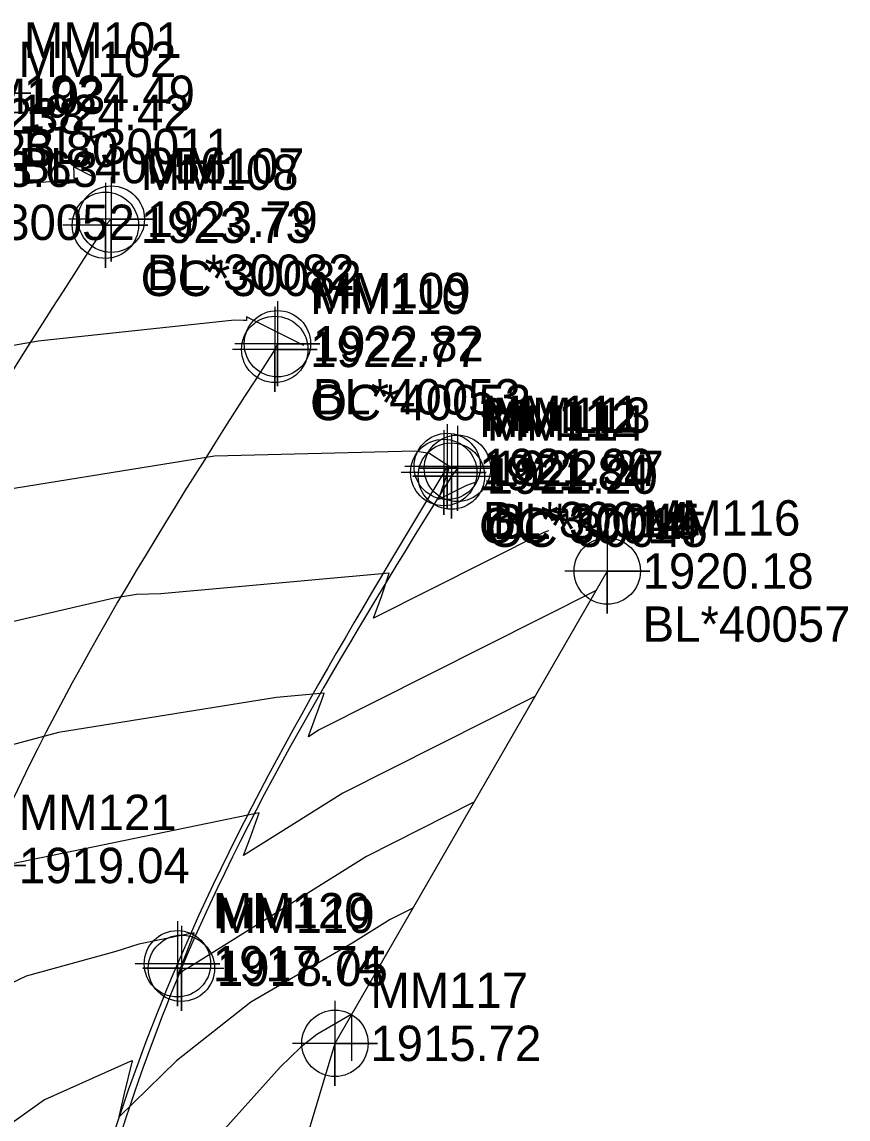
# Model space of a CAD drawing. Extents: x 1004378 to 1005103, y 553854 to 554288.
# Drawn here: x 1005044.7 to 1005103.1, y 554194.9 to 554272.4 of the extents above; entities that cross this region are included whole.
import ezdxf

# ---------------------------------------------------------------- set-up
doc = ezdxf.new("R2010")
doc.units = 0
for name, color, linetype in [('DTM Contours Major', 7, 'Continuous'), ('DTM Contours Minor', 7, 'Continuous'), ('Exist DTM Breakline', 7, 'Continuous'), ('Exist DTM Breakline Cogo Comment', 7, 'Continuous'), ('Exist DTM Breakline Cogo Elevation', 7, 'Continuous'), ('Exist DTM Breakline Cogo Number', 7, 'Continuous'), ('Exist DTM Breakline Cogo Point CELL', 7, 'Continuous'), ('Exist DTM Crownline', 7, 'Continuous'), ('Exist DTM Crownline Cogo Comment', 7, 'Continuous'), ('Exist DTM Crownline Cogo Elevation', 7, 'Continuous'), ('Exist DTM Crownline Cogo Number', 7, 'Continuous'), ('Exist DTM Crownline Cogo Point CELL', 7, 'Continuous'), ('Exist Roads Curbs', 7, 'Continuous'), ('Exist Roads Curbs Cogo Comment', 7, 'Continuous'), ('Exist Roads Curbs Cogo Elevation', 7, 'Continuous'), ('Exist Roads Curbs Cogo Number', 7, 'Continuous'), ('Exist Roads Curbs Cogo Point CELL', 7, 'Continuous'), ('Exist Roads EOP', 7, 'Continuous'), ('Exist Roads EOP Cogo Comment', 7, 'Continuous'), ('Exist Roads EOP Cogo Elevation', 7, 'Continuous'), ('Exist Roads EOP Cogo Number', 7, 'Continuous'), ('Exist Roads EOP Cogo Point CELL', 7, 'Continuous'), ('Exist Roads Soil Cogo Comment', 7, 'Continuous'), ('Exist Roads Soil Cogo Elevation', 7, 'Continuous'), ('Exist Roads Soil Cogo Number', 7, 'Continuous')]:
    doc.layers.add(name, color=color, linetype=linetype)

msp = doc.modelspace()

# ---------------------------------------------------------------- linework, layer by layer
at = {"layer": 'DTM Contours Major'}
msp.add_lwpolyline([(1005085.253, 554232.251), (1005065.7, 554222.397), (1005064.933, 554221.918), (1005064.991, 554222.066), (1005065.344, 554223.049), (1005065.952, 554224.718), (1005066.048, 554225.004), (1005062.678, 554224.698), (1005047.268, 554222.206), (1005031.925, 554218.126), (1005030.77, 554217.777), (1005026.361, 554215.994), (1005026.142, 554215.905), (1005025.965, 554215.797), (1005018.761, 554211.473), (1005015.099, 554208.571), (1005013.055, 554206.965), (1005008.097, 554202.389), (1005006.285, 554199.827), (1005002.41, 554197.77), (1005001.113, 554195.406)], dxfattribs=at)
at = {"layer": 'DTM Contours Minor'}
for points in [[(1005049.674, 554261.493), (1005048.336, 554262.162), (1005048.391, 554261.154), (1005047.971, 554261.002), (1005047.219, 554261.151), (1005038.078, 554260.42), (1005037.81, 554261.029), (1005038.533, 554264.244), (1005038.474, 554264.547), (1005022.134, 554266.393), (1005018.739, 554266.663), (1005008.512, 554259.857), (1005006.97, 554257.736), (1005007.666, 554257.334), (1005003.478, 554254.686), (1004999.082, 554247.727), (1005001.345, 554242.184), (1004999.666, 554238.402), (1004998.854, 554234.12), (1004998.544, 554224.321), (1004997.101, 554219.058), (1004994.148, 554215.354), (1004993.153, 554201.493), (1004985.717, 554187.945)], [(1005064.608, 554249.551), (1005060.552, 554251.578), (1005060.567, 554251.311), (1005060.348, 554251.327), (1005059.72, 554251.352), (1005045.835, 554249.855), (1005031.335, 554247.323)], [(1005076.842, 554239.926), (1005076.104, 554239.672), (1005074.128, 554238.68), (1005074.219, 554238.931), (1005074.736, 554240.465), (1005074.839, 554240.777), (1005074.933, 554240.972), (1005073.435, 554241.951), (1005073.343, 554241.956), (1005072.44, 554242.077), (1005058.295, 554241.729), (1005039.877, 554238.78)], [(1005081.907, 554236.456), (1005081.575, 554236.342), (1005069.531, 554230.299), (1005070.085, 554231.824), (1005070.64, 554233.472), (1005054.504, 554232.01), (1005052.782, 554231.968), (1005051.198, 554231.714), (1005032.836, 554227.453), (1005025.92, 554225.538), (1005021.623, 554223.448), (1005019.859, 554222.732), (1005013.96, 554219.101), (1005012.402, 554218.937), (1005011.71, 554216.413), (1005004.54, 554207.42), (1005004.489, 554206.704), (1004992.311, 554184.516)], [(1005080.939, 554224.769), (1005067.37, 554217.93), (1005060.336, 554213.536), (1005060.866, 554214.898), (1005061.455, 554216.534), (1005042.381, 554212.616), (1005041.766, 554212.425), (1005037.72, 554211.199), (1005036.548, 554210.725), (1005032.718, 554208.659), (1005027.609, 554206.201), (1005022.187, 554202.253), (1005021.549, 554201.814), (1005020.689, 554201.039), (1005013.957, 554194.829)], [(1005076.625, 554217.286), (1005069.041, 554213.464), (1005056.52, 554205.643), (1005056.186, 554205.45), (1005055.751, 554205.106), (1005055.8, 554205.258), (1005055.916, 554205.611), (1005056.742, 554207.729), (1005056.863, 554208.065), (1005052.951, 554207.261), (1005051.317, 554206.753), (1005044.981, 554205.003), (1005038.321, 554201.832), (1005037.92, 554201.653), (1005037.066, 554201.044), (1005029.069, 554195.542), (1005025.438, 554192.269)], [(1005072.311, 554209.804), (1005070.712, 554208.998), (1005068.073, 554207.35), (1005060.854, 554203.169), (1005055.614, 554199.027), (1005051.563, 554195.07), (1005051.936, 554196.712), (1005052.473, 554198.935), (1005052.494, 554198.998), (1005052.502, 554199.025), (1005052.396, 554198.996), (1005052.336, 554198.967), (1005046.282, 554196.261), (1005040.238, 554191.952)], [(1005068.005, 554199.026), (1005067.997, 554202.322), (1005065.521, 554200.888), (1005064.389, 554199.993), (1005062.927, 554198.566), (1005053.023, 554187.546)]]:
    msp.add_lwpolyline(points, dxfattribs=at)
at = {"layer": 'Exist DTM Breakline'}
msp.add_line((1005062.742, 554249.68), (1005062.556, 554249.275), dxfattribs=at)
msp.add_lwpolyline([(1005086.044, 554233.622), (1005066.807, 554200.26), (1005058.407, 554172.308), (1005052.455, 554140.645), (1005052.437, 554096.336), (1005050.24, 554053.656), (1005047.48, 554010.1), (1005047.57, 553964.54), (1005045.226, 553915.523), (1005033.752, 553871.735)], dxfattribs=at)
msp.add_spline([(1005062.556, 554249.275), (1005041.97, 554212.824), (1005032.11, 554179.915), (1005026.833, 554146.301), (1005025.779, 554104.318), (1005027.497, 554055.674)], degree=3, dxfattribs=at)
at = {"layer": 'Exist DTM Breakline Cogo Point CELL'}
for points in [[(1005041.953, 554269.011), (1005041.953, 554263.011), (1005041.953, 554266.011), (1005044.953, 554266.011), (1005038.953, 554266.011)], [(1005062.556, 554252.275), (1005062.556, 554246.275), (1005062.556, 554249.275), (1005065.556, 554249.275), (1005059.556, 554249.275)], [(1005062.742, 554252.68), (1005062.742, 554246.68), (1005062.742, 554249.68), (1005065.742, 554249.68), (1005059.742, 554249.68)], [(1005086.044, 554236.622), (1005086.044, 554230.622), (1005086.044, 554233.622), (1005089.044, 554233.622), (1005083.044, 554233.622)], [(1005041.97, 554215.824), (1005041.97, 554209.824), (1005041.97, 554212.824), (1005044.97, 554212.824), (1005038.97, 554212.824)], [(1005066.807, 554203.26), (1005066.807, 554197.26), (1005066.807, 554200.26), (1005069.807, 554200.26), (1005063.807, 554200.26)]]:
    msp.add_lwpolyline(points, dxfattribs=at)
for centre in [(1005062.742, 554249.68), (1005062.556, 554249.275), (1005086.044, 554233.622), (1005066.807, 554200.26)]:
    msp.add_circle(centre, 2.344, dxfattribs=at)
at = {"layer": 'Exist DTM Crownline'}
msp.add_line((1005051.005, 554258.476), (1005050.587, 554258.044), dxfattribs=at)
msp.add_spline([(1005050.587, 554258.044), (1005028.479, 554219.945), (1005017.046, 554183.931), (1005013.967, 554147.492), (1005013.771, 554103.753), (1005015.769, 554055.214)], degree=3, dxfattribs=at)
at = {"layer": 'Exist DTM Crownline Cogo Point CELL'}
for points in [[(1005051.005, 554261.476), (1005051.005, 554255.476), (1005051.005, 554258.476), (1005054.005, 554258.476), (1005048.005, 554258.476)], [(1005050.587, 554261.044), (1005050.587, 554255.044), (1005050.587, 554258.044), (1005053.587, 554258.044), (1005047.587, 554258.044)]]:
    msp.add_lwpolyline(points, dxfattribs=at)
for centre in [(1005051.005, 554258.476), (1005050.587, 554258.044)]:
    msp.add_circle(centre, 2.344, dxfattribs=at)
at = {"layer": 'Exist Roads Curbs'}
msp.add_line((1005075.456, 554240.876), (1005075.03, 554240.325), dxfattribs=at)
msp.add_spline([(1005075.03, 554240.325), (1005055.961, 554205.561), (1005046.997, 554176.639), (1005041.862, 554143.203), (1005041.439, 554133.575)], degree=3, dxfattribs=at)
at = {"layer": 'Exist Roads Curbs Cogo Point CELL'}
for points in [[(1005075.456, 554243.876), (1005075.456, 554237.876), (1005075.456, 554240.876), (1005072.726, 554240.876), (1005078.456, 554240.876)], [(1005075.03, 554243.325), (1005075.03, 554237.325), (1005075.03, 554240.325), (1005072.3, 554240.325), (1005078.03, 554240.325)], [(1005055.961, 554208.561), (1005055.961, 554202.561), (1005055.961, 554205.561), (1005053.23, 554205.561), (1005058.961, 554205.561)]]:
    msp.add_lwpolyline(points, dxfattribs=at)
for centre in [(1005075.03, 554240.325), (1005075.456, 554240.876), (1005055.961, 554205.561)]:
    msp.add_circle(centre, 2.344, dxfattribs=at)
at = {"layer": 'Exist Roads EOP'}
msp.add_line((1005074.741, 554241.007), (1005074.494, 554240.581), dxfattribs=at)
msp.add_spline([(1005074.494, 554240.581), (1005055.678, 554205.88), (1005046.35, 554176.623), (1005041.386, 554143.248), (1005040.93, 554132.857)], degree=3, dxfattribs=at)
at = {"layer": 'Exist Roads EOP Cogo Point CELL'}
for points in [[(1005042.326, 554270.369), (1005042.326, 554264.369), (1005042.326, 554267.369), (1005045.326, 554267.369), (1005039.326, 554267.369)], [(1005074.494, 554243.581), (1005074.494, 554237.581), (1005074.494, 554240.581), (1005077.494, 554240.581), (1005071.494, 554240.581)], [(1005074.741, 554244.007), (1005074.741, 554238.007), (1005074.741, 554241.007), (1005077.741, 554241.007), (1005071.741, 554241.007)], [(1005055.678, 554208.88), (1005055.678, 554202.88), (1005055.678, 554205.88), (1005058.678, 554205.88), (1005052.678, 554205.88)]]:
    msp.add_lwpolyline(points, dxfattribs=at)
for centre in [(1005074.494, 554240.581), (1005074.741, 554241.007), (1005055.678, 554205.88)]:
    msp.add_circle(centre, 2.344, dxfattribs=at)

# ---------------------------------------------------------------- texts
at = {"layer": 'Exist DTM Breakline Cogo Comment'}
for s, p in [('BL*40056', (1005044.453, 554261.011)), ('OC*40053', (1005065.056, 554244.275)), ('BL*40053', (1005065.242, 554244.68)), ('BL*40057', (1005088.544, 554228.622))]:
    msp.add_text(s, height=2.5, dxfattribs=at).set_placement(p)
at = {"layer": 'Exist DTM Breakline Cogo Elevation'}
for s, p in [('1924.42', (1005044.453, 554264.761)), ('1922.77', (1005065.056, 554248.025)), ('1922.82', (1005065.242, 554248.43)), ('1920.18', (1005088.544, 554232.372)), ('1919.04', (1005044.47, 554211.574)), ('1915.72', (1005069.307, 554199.01))]:
    msp.add_text(s, height=2.5, dxfattribs=at).set_placement(p)
at = {"layer": 'Exist DTM Breakline Cogo Number'}
for s, p in [('MM102', (1005044.453, 554268.511)), ('MM110', (1005065.056, 554251.775)), ('MM109', (1005065.242, 554252.18)), ('MM116', (1005088.544, 554236.122)), ('MM121', (1005044.47, 554215.324)), ('MM117', (1005069.307, 554202.76))]:
    msp.add_text(s, height=2.5, dxfattribs=at).set_placement(p)
at = {"layer": 'Exist DTM Crownline Cogo Comment'}
for s, p in [('BL*30082', (1005053.505, 554253.476)), ('OC*30082', (1005053.087, 554253.044))]:
    msp.add_text(s, height=2.5, dxfattribs=at).set_placement(p)
at = {"layer": 'Exist DTM Crownline Cogo Elevation'}
for s, p in [('1923.79', (1005053.505, 554257.226)), ('1923.73', (1005053.087, 554256.794))]:
    msp.add_text(s, height=2.5, dxfattribs=at).set_placement(p)
at = {"layer": 'Exist DTM Crownline Cogo Number'}
for s, p in [('MM108', (1005053.087, 554260.544)), ('MM107', (1005053.505, 554260.976))]:
    msp.add_text(s, height=2.5, dxfattribs=at).set_placement(p)
at = {"layer": 'Exist Roads Curbs Cogo Comment'}
for s, p in [('BL*30045', (1005077.956, 554235.876)), ('OC*30045', (1005077.53, 554235.325))]:
    msp.add_text(s, height=2.5, dxfattribs=at).set_placement(p)
at = {"layer": 'Exist Roads Curbs Cogo Elevation'}
for s, p in [('1922.27', (1005077.956, 554239.626)), ('1922.20', (1005077.53, 554239.075)), ('1918.05', (1005058.461, 554204.311))]:
    msp.add_text(s, height=2.5, dxfattribs=at).set_placement(p)
at = {"layer": 'Exist Roads Curbs Cogo Number'}
for s, p in [('MM113', (1005077.956, 554243.376)), ('MM114', (1005077.53, 554242.825)), ('MM119', (1005058.461, 554208.061))]:
    msp.add_text(s, height=2.5, dxfattribs=at).set_placement(p)
at = {"layer": 'Exist Roads EOP Cogo Comment'}
for s, p in [('BL*30011', (1005044.826, 554262.369)), ('OC*30014', (1005076.994, 554235.581)), ('BL*30014', (1005077.241, 554236.007))]:
    msp.add_text(s, height=2.5, dxfattribs=at).set_placement(p)
at = {"layer": 'Exist Roads EOP Cogo Elevation'}
for s, p in [('1924.49', (1005044.826, 554266.119)), ('1923.80', (1005039.422, 554262.16)), ('1921.90', (1005077.241, 554239.757)), ('1921.84', (1005076.994, 554239.331)), ('1917.74', (1005058.178, 554204.63))]:
    msp.add_text(s, height=2.5, dxfattribs=at).set_placement(p)
at = {"layer": 'Exist Roads EOP Cogo Number'}
for s, p in [('MM101', (1005044.826, 554269.869)), ('MM103', (1005039.422, 554265.91)), ('MM111', (1005077.241, 554243.507)), ('MM112', (1005076.994, 554243.081)), ('MM120', (1005058.178, 554208.38))]:
    msp.add_text(s, height=2.5, dxfattribs=at).set_placement(p)
at = {"layer": 'Exist Roads Soil Cogo Comment'}
msp.add_text('BL*30052', height=2.5, dxfattribs=at).set_placement((1005037.976, 554257.003))
at = {"layer": 'Exist Roads Soil Cogo Elevation'}
msp.add_text('1923.63', height=2.5, dxfattribs=at).set_placement((1005037.976, 554260.753))
at = {"layer": 'Exist Roads Soil Cogo Number'}
msp.add_text('MM238', height=2.5, dxfattribs=at).set_placement((1005037.976, 554264.503))

doc.saveas('drawing.dxf')
